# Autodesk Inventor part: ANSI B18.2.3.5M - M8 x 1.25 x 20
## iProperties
Comments: To add or edit properties for Autodesk Inventor files, use iProperties.
Created: 2004-07
Part Number: ANSI B18.2.3.5M - M8 x 1.25 x 20
Vendor: Autodesk Inc.
Document SubType Name: Modeling
Designer: John Blackburn
Material: Default
Description: Hex Bolt
Standard: ANSI B18.2.3.5M
Size Designation: M8 x 1.25 x 20
Alert: To add or edit properties for Autodesk Inventor files, use iProperties.
Control State: 0
Master: False
Checked Out: False
Shininess: 64.0
Length Units: 11269
Angle Units: 11279
Time Units: 11290
Mass Units: 11283
Length Display Precision: 3
Angle Display Precision: 2
Compacted: True
EGR: 1
Classification: un/spsc 31161513
Density: 0.0
Volumn: 0.0
Area: 0.0
PropertySet Name: Model Information
Author: John Blackburn
Revision Number: 8
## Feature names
1. Body [Revolution]
2. Head [Extrusion]
3. Chamfer1 [Revolution]
4. Chamfer2
